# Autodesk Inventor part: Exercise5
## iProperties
Created: 2002-02
Part Number: Exercise5
Document SubType Name: Modeling
Control State: 0
Master: False
Checked Out: False
Shininess: 64.0
Length Units: 11269
Angle Units: 11279
Time Units: 11290
Mass Units: 11283
Length Display Precision: 3
Angle Display Precision: 2
Compacted: True
Density: 0.0
Volumn: 0.0
Area: 0.0
PropertySet Name: Model Information
